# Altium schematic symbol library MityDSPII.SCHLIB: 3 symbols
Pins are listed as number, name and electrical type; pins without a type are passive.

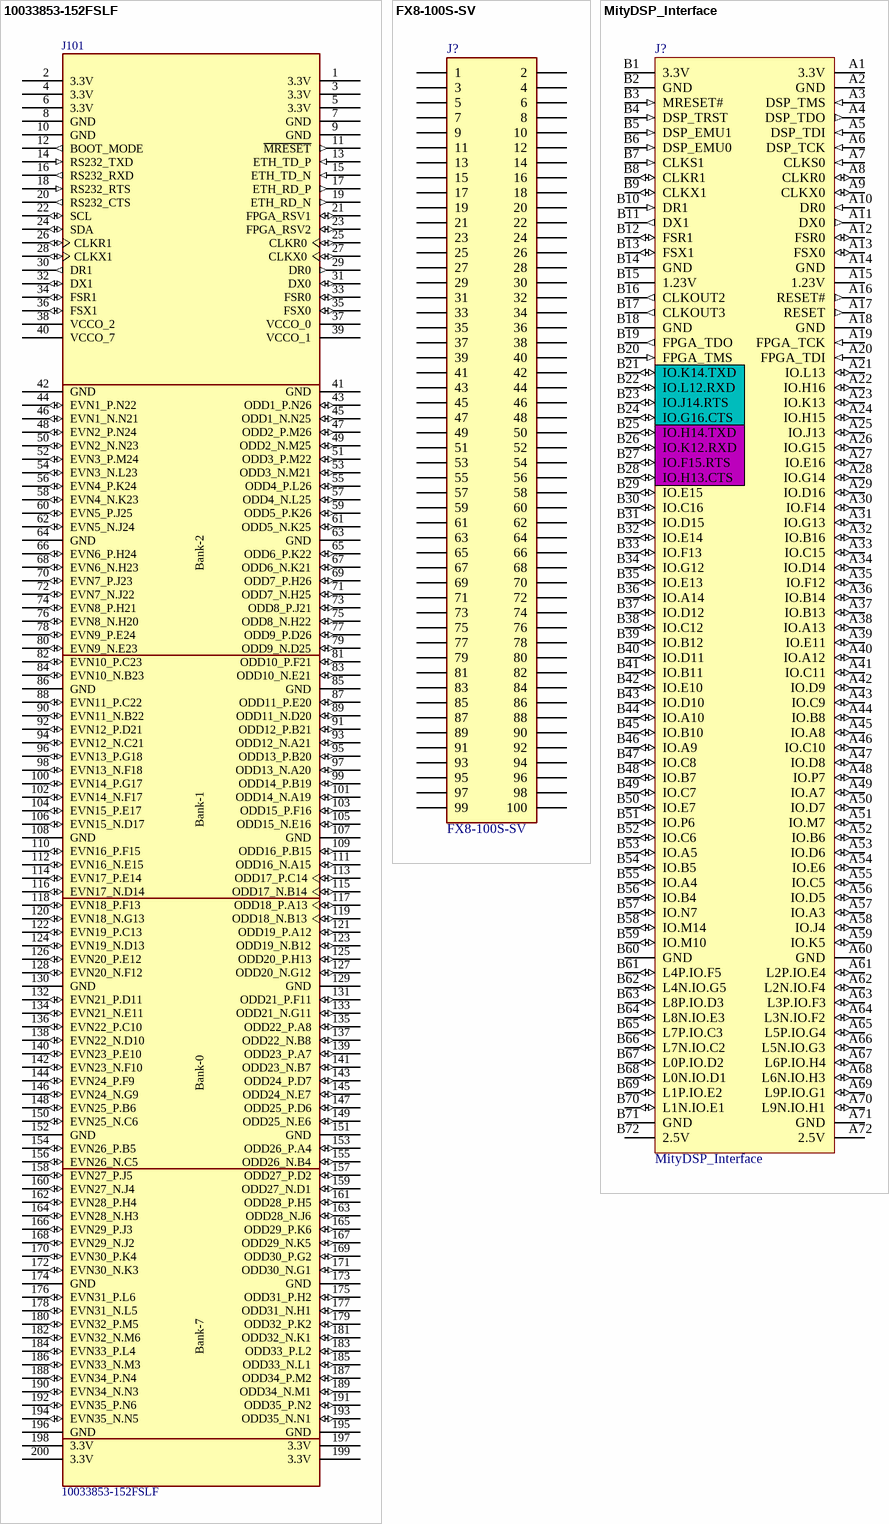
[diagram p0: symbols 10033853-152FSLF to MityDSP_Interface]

## 10033853-152FSLF
designator J101
CONN SODIMM DDR2 200POS R/A SMD; Dist1: Digi-Key; Dist1_PN: 609-1007-ND; Mfg: FCI; User: Alexei
footprint 10033853-152FSLF (CONN SODIMM DDR2 200POS R/A SMD)
pins: 1 3.3V (power), 2 3.3V (power), 3 3.3V (power), 4 3.3V (power), 5 3.3V (power), 6 3.3V (power), 7 GND (power), 8 GND (power), 9 GND (power), 10 GND (power), 11 ~{MRESET} (out), 12 BOOT_MODE (out), 13 ETH_TD_P (in), 14 RS232_TXD (in), 15 ETH_TD_N (in), 16 RS232_RXD (out), 17 ETH_RD_P (out), 18 RS232_RTS (in), 19 ETH_RD_N (out), 20 RS232_CTS (out), 21 FPGA_RSV1 (io), 22 SCL (io), 23 FPGA_RSV2 (io), 24 SDA (io), 25 CLKR0 (io), 26 CLKR1 (io), 27 CLKX0 (io), 28 CLKX1 (io), 29 DR0 (out), 30 DR1 (out), 31 DX0 (io), 32 DX1 (io), 33 FSR0 (io), 34 FSR1 (io), 35 FSX0 (io), 36 FSX1 (io), 37 VCCO_0 (power), 38 VCCO_2 (power), 39 VCCO_1 (power), 40 VCCO_7 (power), 41 GND (power), 42 GND (power), 43 ODD1_P.N26 (io), 44 EVN1_P.N22 (io), 45 ODD1_N.N25 (io), 46 EVN1_N.N21 (io), 47 ODD2_P.M26 (io), 48 EVN2_P.N24 (io), 49 ODD2_N.M25 (io), 50 EVN2_N.N23 (io), 51 ODD3_P.M22 (io), 52 EVN3_P.M24 (io), 53 ODD3_N.M21 (io), 54 EVN3_N.L23 (io), 55 ODD4_P.L26 (io), 56 EVN4_P.K24 (io), 57 ODD4_N.L25 (io), 58 EVN4_N.K23 (io), 59 ODD5_P.K26 (io), 60 EVN5_P.J25 (io), 61 ODD5_N.K25 (io), 62 EVN5_N.J24 (io), 63 GND (power), 64 GND (power), 65 ODD6_P.K22 (io), 66 EVN6_P.H24 (io), 67 ODD6_N.K21 (io), 68 EVN6_N.H23 (io), 69 ODD7_P.H26 (io), 70 EVN7_P.J23 (io), 71 ODD7_N.H25 (io), 72 EVN7_N.J22 (io), 73 ODD8_P.J21 (io), 74 EVN8_P.H21 (io), 75 ODD8_N.H22 (io), 76 EVN8_N.H20 (io), 77 ODD9_P.D26 (io), 78 EVN9_P.E24 (io), 79 ODD9_N.D25 (io), 80 EVN9_N.E23 (io), 81 ODD10_P.F21 (io), 82 EVN10_P.C23 (io), 83 ODD10_N.E21 (io), 84 EVN10_N.B23 (io), 85 GND (power), 86 GND (power), 87 ODD11_P.E20 (io), 88 EVN11_P.C22 (io), 89 ODD11_N.D20 (io), 90 EVN11_N.B22 (io), 91 ODD12_P.B21 (io), 92 EVN12_P.D21 (io), 93 ODD12_N.A21 (io), 94 EVN12_N.C21 (io), 95 ODD13_P.B20 (io), 96 EVN13_P.G18 (io), 97 ODD13_N.A20 (io), 98 EVN13_N.F18 (io), 99 ODD14_P.B19 (io), 100 EVN14_P.G17 (io), 101 ODD14_N.A19 (io), 102 EVN14_N.F17 (io), 103 ODD15_P.F16 (io), 104 EVN15_P.E17 (io), 105 ODD15_N.E16 (io), 106 EVN15_N.D17 (io), 107 GND (power), 108 GND (power), 109 ODD16_P.B15 (io), 110 EVN16_P.F15 (io), 111 ODD16_N.A15 (io), 112 EVN16_N.E15 (io), 113 ODD17_P.C14 (io), 114 EVN17_P.E14 (io), 115 ODD17_N.B14 (io), 116 EVN17_N.D14 (io), 117 ODD18_P.A13 (io), 118 EVN18_P.F13 (io), 119 ODD18_N.B13 (io), 120 EVN18_N.G13 (io), 121 ODD19_P.A12 (io), 122 EVN19_P.C13 (io), 123 ODD19_N.B12 (io), 124 EVN19_N.D13 (io), 125 ODD20_P.H13 (io), 126 EVN20_P.E12 (io), 127 ODD20_N.G12 (io), 128 EVN20_N.F12 (io), 129 GND (power), 130 GND (power), 131 ODD21_P.F11 (io), 132 EVN21_P.D11 (io), 133 ODD21_N.G11 (io), 134 EVN21_N.E11 (io), 135 ODD22_P.A8 (io), 136 EVN22_P.C10 (io), 137 ODD22_N.B8 (io), 138 EVN22_N.D10 (io), 139 ODD23_P.A7 (io), 140 EVN23_P.E10 (io), 141 ODD23_N.B7 (io), 142 EVN23_N.F10 (io), 143 ODD24_P.D7 (io), 144 EVN24_P.F9 (io), 145 ODD24_N.E7 (io), 146 EVN24_N.G9 (io), 147 ODD25_P.D6 (io), 148 EVN25_P.B6 (io), 149 ODD25_N.E6 (io), 150 EVN25_N.C6 (io), 151 GND (power), 152 GND (power), 153 ODD26_P.A4 (io), 154 EVN26_P.B5 (io), 155 ODD26_N.B4 (io), 156 EVN26_N.C5 (io), 157 ODD27_P.D2 (io), 158 EVN27_P.J5 (io), 159 ODD27_N.D1 (io), 160 EVN27_N.J4 (io), 161 ODD28_P.H5 (io), 162 EVN28_P.H4 (io), 163 ODD28_N.J6 (io), 164 EVN28_N.H3 (io), 165 ODD29_P.K6 (io), 166 EVN29_P.J3 (io), 167 ODD29_N.K5 (io), 168 EVN29_N.J2 (io), 169 ODD30_P.G2 (io), 170 EVN30_P.K4 (io), 171 ODD30_N.G1 (io), 172 EVN30_N.K3 (io), 173 GND (power), 174 GND (power), 175 ODD31_P.H2 (io), 176 EVN31_P.L6 (io), 177 ODD31_N.H1 (io), 178 EVN31_N.L5 (io), 179 ODD32_P.K2 (io), 180 EVN32_P.M5 (io), 181 ODD32_N.K1 (io), 182 EVN32_N.M6 (io), 183 ODD33_P.L2 (io), 184 EVN33_P.L4 (io), 185 ODD33_N.L1 (io), 186 EVN33_N.M3 (io), 187 ODD34_P.M2 (io), 188 EVN34_P.N4 (io), 189 ODD34_N.M1 (io), 190 EVN34_N.N3 (io), 191 ODD35_P.N2 (io), 192 EVN35_P.N6 (io), 193 ODD35_N.N1 (io), 194 EVN35_N.N5 (io), 195 GND (power), 196 GND (power), 197 3.3V (power), 198 3.3V (power), 199 3.3V (power), 200 3.3V (power)

## FX8-100S-SV
designator J?
CONN RECEPT 100POS .6MM GOLD SMD; User: MikeP; Dist1: Newark; Dist1_PN: 34M6266; Mfg: Hirose; Mfg_PN: FX8-100S-SV(21); $/100: 4.210000; $/500: 3.620000; $/ea: 0.000000; Mfg_PID: 4372; PbFree_Status: Lead Free; QtyAvail: 0; dist_PID: 4382; dist_pref: 100; ID: 3734
footprint FX8-100S-SV (FX8 Series receptacle, 100 contacts)
pins: 1, 2, 3, 4, 5, 6, 7, 8, 9, 10, 11, 12, 13, 14, 15, 16, 17, 18, 19, 20, 21, 22, 23, 24, 25, 26, 27, 28, 29, 30, 31, 32, 33, 34, 35, 36, 37, 38, 39, 40, 41, 42, 43, 44, 45, 46, 47, 48, 49, 50, 51, 52, 53, 54, 55, 56, 57, 58, 59, 60, 61, 62, 63, 64, 65, 66, 67, 68, 69, 70, 71, 72, 73, 74, 75, 76, 77, 78, 79, 80, 81, 82, 83, 84, 85, 86, 87, 88, 89, 90, 91, 92, 93, 94, 95, 96, 97, 98, 99, 100

## MityDSP_Interface
designator J?
CONN SOCKET 144 POS DIMM AU SMD; Mfg: Tyco Electronics; Mfg_PN: 390110-1; User: MikeP; $/100: 5.120000; $/500: 4.249600; $/ea: 7.680000; Dist1: Digi-Key; Dist1_PN: 390110-1-ND; QtyAvail: 1088; PbFree_Status: Contains Lead; ID: 17; Mfg_PID: 3024
footprint 390110-1- Clip
pins: A1 3.3V (power), A2 GND (power), A3 DSP_TMS (in), A4 DSP_TDO (out), A5 DSP_TDI (in), A6 DSP_TCK (in), A7 CLKS0 (in), A8 CLKR0 (io), A9 CLKX0 (io), A10 DR0 (in), A11 DX0 (out), A12 FSR0 (io), A13 FSX0 (io), A14 GND (power), A15 1.23V (power), A16 RESET# (out), A17 RESET (out), A18 GND (power), A19 FPGA_TCK (in), A20 FPGA_TDI (in), A21 IO.L13 (io) "FPGA_IO", A22 IO.H16 (io) "FPGA_IO", A23 IO.K13 (io) "FPGA_IO", A24 IO.H15 (io) "FPGA_IO", A25 IO.J13 (io) "FPGA_IO", A26 IO.G15 (io) "FPGA_IO", A27 IO.E16 (io) "FPGA_IO", A28 IO.G14 (io) "FPGA_IO", A29 IO.D16 (io) "FPGA_IO", A30 IO.F14 (io) "FPGA_IO", A31 IO.G13 (io) "FPGA_IO", A32 IO.B16 (io) "FPGA_IO", A33 IO.C15 (io) "FPGA_IO", A34 IO.D14 (io) "FPGA_IO", A35 IO.F12 (io) "FPGA_IO", A36 IO.B14 (io) "FPGA_IO", A37 IO.B13 (io) "FPGA_IO", A38 IO.A13 (io) "FPGA_IO", A39 IO.E11 (io) "FPGA_IO", A40 IO.A12 (io) "FPGA_IO", A41 IO.C11 (io) "FPGA_IO", A42 IO.D9 (io) "FPGA_IO", A43 IO.C9 (io) "FPGA_IO", A44 IO.B8 (io) "FPGA_IO", A45 IO.A8 (io) "FPGA_IO", A46 IO.C10 (io) "FPGA_IO", A47 IO.D8 (io) "FPGA_IO", A48 IO.P7 (io) "FPGA_IO", A49 IO.A7 (io) "FPGA_IO", A50 IO.D7 (io) "FPGA_IO", A51 IO.M7 (io) "FPGA_IO", A52 IO.B6 (io) "FPGA_IO", A53 IO.D6 (io) "FPGA_IO", A54 IO.E6 (io) "FPGA_IO", A55 IO.C5 (io) "FPGA_IO", A56 IO.D5 (io) "FPGA_IO", A57 IO.A3 (io) "FPGA_IO", A58 IO.J4 (io) "FPGA_IO", A59 IO.K5 (io) "FPGA_IO", A60 GND (power), A61 L2P.IO.E4 (io) "LVDS/FPGA_IO", A62 L2N.IO.F4 (io) "LVDS/FPGA_IO", A63 L3P.IO.F3 (io) "LVDS/FPGA_IO", A64 L3N.IO.F2 (io) "LVDS/FPGA_IO", A65 L5P.IO.G4 (io) "LVDS/FPGA_IO", A66 L5N.IO.G3 (io) "LVDS/FPGA_IO", A67 L6P.IO.H4 (io) "LVDS/FPGA_IO", A68 L6N.IO.H3 (io) "LVDS/FPGA_IO", A69 L9P.IO.G1 (io) "LVDS/FPGA_IO", A70 L9N.IO.H1 (io) "LVDS/FPGA_IO", A71 GND (power), A72 2.5V (power), B1 3.3V (power), B2 GND (power), B3 MRESET# (in), B4 DSP_TRST (in), B5 DSP_EMU1 (in), B6 DSP_EMU0 (in), B7 CLKS1 (in), B8 CLKR1 (io), B9 CLKX1 (io), B10 DR1 (in), B11 DX1 (out), B12 FSR1 (io), B13 FSX1 (io), B14 GND (power), B15 1.23V (power), B16 CLKOUT2 (out), B17 CLKOUT3 (out), B18 GND (power), B19 FPGA_TDO (out), B20 FPGA_TMS (in), B21 IO.K14.TXD (io) "FPGA_IO", B22 IO.L12.RXD (io) "FPGA_IO", B23 IO.J14.RTS (io) "FPGA_IO", B24 IO.G16.CTS (io) "FPGA_IO", B25 IO.H14.TXD (io) "FPGA_IO", B26 IO.K12.RXD (io) "FPGA_IO", B27 IO.F15.RTS (io) "FPGA_IO", B28 IO.H13.CTS (io) "FPGA_IO", B29 IO.E15 (io) "FPGA_IO", B30 IO.C16 (io) "FPGA_IO", B31 IO.D15 (io) "FPGA_IO", B32 IO.E14 (io) "FPGA_IO", B33 IO.F13 (io) "FPGA_IO", B34 IO.G12 (io) "FPGA_IO", B35 IO.E13 (io) "FPGA_IO", B36 IO.A14 (io) "FPGA_IO", B37 IO.D12 (io) "FPGA_IO", B38 IO.C12 (io) "FPGA_IO", B39 IO.B12 (io) "FPGA_IO", B40 IO.D11 (io) "FPGA_IO", B41 IO.B11 (io) "FPGA_IO", B42 IO.E10 (io) "FPGA_IO", B43 IO.D10 (io) "FPGA_IO", B44 IO.A10 (io) "FPGA_IO", B45 IO.B10 (io) "FPGA_IO", B46 IO.A9 (io) "FPGA_IO", B47 IO.C8 (io) "FPGA_IO", B48 IO.B7 (io) "FPGA_IO", B49 IO.C7 (io) "FPGA_IO", B50 IO.E7 (io) "FPGA_IO", B51 IO.P6 (io) "FPGA_IO", B52 IO.C6 (io) "FPGA_IO", B53 IO.A5 (io) "FPGA_IO", B54 IO.B5 (io) "FPGA_IO", B55 IO.A4 (io) "FPGA_IO", B56 IO.B4 (io) "FPGA_IO", B57 IO.N7 (io) "FPGA_IO", B58 IO.M14 (io) "FPGA_IO", B59 IO.M10 (io) "FPGA_IO", B60 GND (power), B61 L4P.IO.F5 (io) "LVDS/FPGA_IO", B62 L4N.IO.G5 (io) "LVDS/FPGA_IO", B63 L8P.IO.D3 (io) "LVDS/FPGA_IO", B64 L8N.IO.E3 (io) "LVDS/FPGA_IO", B65 L7P.IO.C3 (io) "LVDS/FPGA_IO", B66 L7N.IO.C2 (io) "LVDS/FPGA_IO", B67 L0P.IO.D2 (io) "LVDS/FPGA_IO", B68 L0N.IO.D1 (io) "LVDS/FPGA_IO", B69 L1P.IO.E2 (io) "LVDS/FPGA_IO", B70 L1N.IO.E1 (io) "LVDS/FPGA_IO", B71 GND (power), B72 2.5V (power)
